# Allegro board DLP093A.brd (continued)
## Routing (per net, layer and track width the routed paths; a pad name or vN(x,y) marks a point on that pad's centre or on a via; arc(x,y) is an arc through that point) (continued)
DDBP13: length 61.9
  06_SIG2 w0.094: v1(51.81,58.2) 51.81,58.6 51.7,58.71 51.55,58.71 51.3,58.46 51.3,56.19 50.87,55.76 47.83,55.76 47.35,55.28 47.35,47.22 48.56,46.01 48.56,41.22 48.25,40.91 47.65,40.91 47.31,41.26 47.31,45.34 47.12,45.53 46.76,45.53 46.57,45.34 46.57,41.21 46.26,40.9 45.56,40.9 45.25,41.21 45.25,45.41 45.07,45.59 44.7,45.59 44.48,45.36 44.48,40.43 44.77,40.14 50.76,40.14 54.01,36.89 54.01,32.86 53.55,32.4 53.22,32.4 53.11,32.29 v1(53.11,31.89)
  BOTTOM w0.213: U500.R20 v1(53.11,31.89)
DDBP15: length 61.9
  04_SIG1 w0.094: v1(53.08,56.93) 52.79,56.93 52.67,57.05 52.67,57.33 52.82,57.48 53.58,57.48 54.21,56.84 54.21,48.95 52.57,47.31 52.57,41.91 52.35,41.69 51.88,41.69 51.65,41.92 51.65,47.52 53.43,49.3 53.43,55.82 53.11,56.14 52.49,56.14 52.17,55.83 52.17,49.8 50.4,48.03 50.4,40.4 51.37,39.43 51.37,35.05 52.35,34.07 52.35,32.85 52.15,32.65 51.95,32.65 51.84,32.76 v1(51.84,33.16)
  BOTTOM w0.213: v1(51.84,33.16) U500.T19
DMDRSTZ: length 145.6
  TOP w0.187: v1(78.25,36.45) 77.94,36.76 U1.59
  04_SIG1 w0.135: v1(35.3,62.01) 35.97,61.34 36.86,61.34 37.2,61 37.2,56.44 36.15,55.39 36.15,48.25 26.08,38.18 26.08,15.85 26.65,15.28 31.87,15.28 v1(33.05,14.11) 43.28,3.88 77.92,3.88 78.51,4.47 78.51,13.3 TP25.1 78.65,16.47 78.65,36.05 v1(78.25,36.45)
  BOTTOM w0.213: v1(33.05,14.11) U500.B9
MBRST0: length 85.1
  TOP w0.178: U1.22 v1(68.23,48.79)
  04_SIG1 w0.135: v1(68.23,48.79) 68.27,48.79 69.02,48.04 69.02,46.04 68.57,45.59 67.94,45.59 66.98,44.63 66.98,40.17 67.32,39.84 67.32,30.41 62.28,25.37 62.28,18.74 TP2.1
  06_SIG2 w0.135: v1(25.43,15.38) 26.08,14.73 26.08,13.84 26.42,13.51 38.7,13.51 40.06,12.14 47.72,12.14 48.17,11.7 58.58,11.7 59.33,12.45 63.32,12.45 TP2.1
  BOTTOM w0.178: v1(25.43,15.38) U500.C3
MBRST1: length 99.1
  TOP w0.178: U1.24 v1(68.23,47.79)
  04_SIG1 w0.135: TP3.1 61.11,13.05 61.11,25.98 64.75,29.62 64.75,37.79 64.95,37.99 64.95,41.03 64.69,41.28 64.69,44.48 65.32,45.1 65.84,45.1 68.23,47.49 v1(68.23,47.79)
  06_SIG2 w0.135: v1(24.16,16.65) 23.75,16.65 23.15,16.05 22.56,16.05 22.25,15.74 22.25,13.64 26.21,9.68 48.7,9.68 49.07,10.06 59.88,10.06 60.56,10.74 63.42,10.74 TP3.1
  BOTTOM w0.178: v1(24.16,16.65) U500.D2
MBRST2: length 91.7
  TOP w0.178: U1.27 v1(68.23,46.29)
  04_SIG1 w0.135: TP4.1 66.47,13.66 66,13.66 61.67,17.98 61.67,25.6 66.67,30.61 66.67,39.57 66.42,39.83 66.42,44.91 67.8,46.29 v1(68.23,46.29)
  06_SIG2 w0.135: v1(25.43,16.65) 25.43,16.23 24.78,15.58 24.78,12.63 26.62,10.79 48,10.79 48.37,11.17 59.02,11.17 59.74,11.9 TP4.1
  BOTTOM w0.178: v1(25.43,16.65) U500.D3
MBRST3: length 98.9
  TOP w0.178: U1.29 68.01,45.29 68.28,45.02 v1(68.28,44.99)
  04_SIG1 w0.135: TP5.1 71.03,11.92 63.04,19.91 63.04,25.31 67.84,30.1 67.84,40.19 67.61,40.42 67.61,44.18 68.18,44.75 68.18,44.88 v1(68.28,44.99)
  06_SIG2 w0.135: TP5.1 65.48,9.74 63.95,11.27 60,11.27 59.34,10.61 48.58,10.61 48.19,10.22 26.41,10.22 23.54,13.09 23.54,15.64 23.92,16.02 24.39,16.02 24.78,16.41 24.78,17.3 v1(24.16,17.92)
  BOTTOM w0.178: v1(24.16,17.92) U500.E2
MBRST4: length 107.7
  TOP w0.178: U1.32 v1(68.23,43.79)
  04_SIG1 w0.135: TP6.1 60.54,10.07 60.54,26.4 63.93,29.79 63.93,37.8 64.43,38.29 64.43,40.35 64.01,40.77 64.01,45.04 65.4,46.43 66.07,46.43 67.47,47.83 67.47,48.89 67.98,49.4 68.77,49.4 69.12,49.05 70.14,49.05 70.6,48.6 70.6,46.23 68.23,43.87 v1(68.23,43.79)
  06_SIG2 w0.135: v1(25.43,20.46) 24.76,19.79 24.76,18.95 24.35,18.54 22.63,18.54 21.1,17.01 21.1,13.25 25.74,8.61 49.38,8.61 49.73,8.96 60.35,8.96 60.63,9.23 TP6.1
  BOTTOM w0.178: v1(25.43,20.46) U500.G3
MBRST5: length 104.6
  TOP w0.178: U1.34 v1(68.23,42.79)
  04_SIG1 w0.135: v1(68.23,42.79) 69.04,41.99 69.04,39.75 68.36,39.07 68.36,29.87 63.61,25.12 63.61,20.52 73.57,10.56 73.57,7.98 TP7.1
  06_SIG2 w0.135: TP7.1 72.45,6.86 65.46,6.86 62.14,10.18 60.76,10.18 60.11,9.53 49.56,9.53 49.15,9.13 26.01,9.13 21.66,13.48 21.66,16.7 v1(22.89,17.92)
  BOTTOM w0.178: v1(22.89,17.92) U500.E1
MBRST6: length 111.7
  TOP w0.178: TP8.1 70.9,12.03 62.94,19.99 62.94,36.47 64.79,38.31 64.79,40.31 65.76,41.29 U1.37
  06_SIG2 w0.135: v1(24.16,20.46) 23.56,19.86 22.58,19.86 20.58,17.87 20.58,12.68 26.19,7.07 49.51,7.07 50.81,8.37 62,8.37 64.2,6.17 73.13,6.17 74.67,7.71 74.67,11.05 TP8.1
  BOTTOM w0.178: v1(24.16,20.46) U500.G2
MBRST7: length 113.4
  TOP w0.178: U1.39 67.87,40.29 68.15,40 68.15,38.15 63.79,33.79 63.79,20.66 69.63,14.82 TP9.1
  06_SIG2 w0.135: TP9.1 73.19,14.82 75.22,12.79 75.22,7.39 73.46,5.63 63.67,5.63 61.49,7.8 51.35,7.8 50.05,6.5 24.92,6.5 20.04,11.38 20.04,18.24 22.25,20.46 v1(22.89,20.46)
  BOTTOM w0.178: v1(22.89,20.46) U500.G1
MBRST8: length 134.4
  TOP w0.178: U1.62 v1(81.7,40.29)
  04_SIG1 w0.135: TP10.1 82.35,8.87 82.35,25.15 81.7,25.8 81.7,34.35 82.47,35.12 82.47,37.3 81.7,38.08 v1(81.7,40.29)
  06_SIG2 w0.135: TP10.1 80.93,5.96 77.32,2.35 24.27,2.35 15.84,10.78 15.84,19.52 21.63,25.32 21.63,29.98 22.19,30.53 24.57,30.53 25.43,29.67 v1(25.43,29.35)
  BOTTOM w0.178: v1(25.43,29.35) U500.N3
MBRST9: length 121.8
  TOP w0.178: v1(81.7,41.3) 81.68,41.29 U1.64
  04_SIG1 w0.135: v1(81.7,41.3) 81.04,40.65 81.04,37.88 81.92,37.01 81.92,35.32 81.04,34.45 81.04,25.41 81.66,24.79 81.66,18.22 TP11.1
  06_SIG2 w0.135: TP11.1 77.33,13.88 77.33,7.86 74,4.53 25.27,4.53 18.87,10.92 18.87,19.46 22.37,22.96 23.72,22.96 24.77,24.01 24.77,27.47 v1(24.16,28.08)
  BOTTOM w0.178: v1(24.16,28.08) U500.M2
MBRST10: length 135.7
  TOP w0.178: U1.67 81.61,42.79 81.77,42.95 v1(81.77,43.31)
  04_SIG1 w0.135: v1(81.77,43.31) 82.28,43.31 83.19,42.4 83.19,37.99 84.02,37.16 84.02,35.16 82.75,33.9 82.75,28.86 83.14,28.48 83.14,15.79 TP12.1
  06_SIG2 w0.135: TP12.1 84.24,13.62 79.44,8.83 79.44,5.22 77.13,2.91 24.5,2.91 16.42,10.99 16.42,19.31 22.06,24.95 23.14,24.95 23.5,25.31 23.5,28.35 23.84,28.69 24.44,28.69 25.05,28.08 v1(25.43,28.08)
  BOTTOM w0.178: v1(25.43,28.08) U500.M3
MBRST11: length 120.8
  TOP w0.178: U1.69 81.31,43.79 81.77,44.24 v1(82.29,44.24)
  04_SIG1 w0.135: v1(24.16,26.81) 23.57,26.22 23.57,15.03 23.91,14.69 30.76,14.69 31.12,14.32 31.12,13.87 31.53,13.46 32.03,13.46 32.4,13.09 32.4,12.52 41.59,3.33 78.58,3.33 TP13.1 85.6,10.34 85.6,36.87 84.19,38.28 84.19,42.51 82.45,44.24 v1(82.29,44.24)
  BOTTOM w0.178: v1(24.16,26.81) U500.L2
MBRST12: length 138.6
  TOP w0.178: v1(81.7,45.3) 81.68,45.29 U1.72
  04_SIG1 w0.135: TP14.1 75.23,18.38 75.23,30.09 74.39,30.93 74.39,34.59 75.49,35.69 75.49,37.19 75.7,37.4 75.7,39.74 76.52,40.56 76.52,48.32 79.26,51.06 83.03,51.06 84.31,49.77 84.31,47.02 82.6,45.3 v1(81.7,45.3)
  06_SIG2 w0.135: TP14.1 75.98,15.33 75.98,7.36 73.7,5.08 63.18,5.08 61.03,7.24 51.93,7.24 50.63,5.94 24.62,5.94 19.43,11.13 19.43,19.17 22.64,22.37 23.89,22.37 25.43,23.91 v1(25.43,24.27)
  BOTTOM w0.178: v1(25.43,24.27) U500.J3
MBRST13: length 117.9
  TOP w0.178: v1(83.02,46.74) 82.57,46.29 U1.74
  04_SIG1 w0.135: TP15.1 76.87,30.46 77.6,31.19 77.6,37.93 76.95,38.57 76.95,39.42 77.42,39.89 77.97,39.89 78.4,40.32 78.4,46.62 81.63,49.85 82.5,49.85 83.71,48.64 83.71,47.43 v1(83.02,46.74)
  06_SIG2 w0.135: v1(22.89,26.81) 22.24,27.45 22.24,29.57 22.65,29.98 24.38,29.98 24.77,29.59 24.77,29.18 25.2,28.75 25.65,28.75 26.02,28.38 26.02,15.85 27.03,14.83 48.1,14.83 48.68,14.25 48.68,12.69 49.11,12.25 58.22,12.25 59.05,13.09 62.58,13.09 65.8,16.3 71.09,16.3 74.94,20.15 TP15.1
  BOTTOM w0.178: v1(22.89,26.81) U500.L1
MBRST14: length 127.2
  TOP w0.178: v1(82.02,48.12) 81.83,48.12 81.5,47.79 U1.77
  04_SIG1 w0.135: TP16.1 80.42,23.33 80.42,46.71 81.83,48.12 v1(82.02,48.12)
  06_SIG2 w0.135: TP16.1 82.28,21.47 82.28,16.7 78.03,12.45 78.03,7.68 74.36,4 25,4 18.31,10.69 18.31,19.71 22.14,23.54 23.42,23.54 v1(24.16,24.27)
  BOTTOM w0.178: v1(24.16,24.27) U500.J2
MBRST15: length 129.2
  TOP w0.178: U1.79 81.57,48.79 v1(81.91,49.13)
  04_SIG1 w0.135: TP17.1 79.78,13.81 79.78,47 v1(81.91,49.13)
  06_SIG2 w0.135: v1(22.89,24.27) 22.11,24.27 16.95,19.11 16.95,11.26 24.79,3.43 74.75,3.43 78.71,7.39 78.71,10.19 TP17.1
  BOTTOM w0.178: v1(22.89,24.27) U500.J1
MODE_A: length 5.4
  TOP w0.187: v1(26.7,12.84) 26.45,12.59 R2.1 R1.2
  BOTTOM w0.213: v1(26.7,12.84) U500.A4
Net_122:
  vias: v1(42.92,60.74)
Net_123:
  vias: v1(42.92,62.01)
Net_124:
  vias: v1(44.19,62.01)
Net_125:
  vias: v1(44.19,63.28)
Net_126:
  vias: v1(45.46,60.74)
Net_127:
  vias: v1(45.46,62.01)
Net_128:
  vias: v1(48,60.74)
Net_129:
  vias: v1(48,62.01)
Net_130:
  vias: v1(49.27,62.01)
Net_131:
  vias: v1(49.27,63.28)
Net_132:
  vias: v1(50.54,60.74)
Net_133:
  vias: v1(50.54,62.01)
Net_134:
  vias: v1(51.81,62.01)
Net_135:
  vias: v1(51.81,63.28)
Net_136:
  vias: v1(23.87,62.01)
Net_137:
  vias: v1(23.87,63.28)
Net_138:
  vias: v1(25.14,60.74)
Net_139:
  vias: v1(25.14,62.01)
Net_140:
  vias: v1(26.41,62.01)
Net_141:
  vias: v1(26.41,63.28)
Net_142:
  vias: v1(27.68,60.74)
Net_143:
  vias: v1(27.68,62.01)
Net_144:
  vias: v1(30.22,60.74)
Net_145:
  vias: v1(30.22,62.01)
Net_146:
  vias: v1(31.49,62.01)
Net_147:
  vias: v1(31.49,63.28)
Net_148:
  vias: v1(32.76,60.74)
Net_149:
  vias: v1(32.76,62.01)
Net_150:
  vias: v1(34.03,62.01)
Net_151:
  vias: v1(34.03,63.28)
Net_152:
  vias: v1(35.3,56.93)
Net_153:
  vias: v1(36.57,59.47)
Net_154:
  vias: v1(36.57,62.01)
Net_155:
  vias: v1(41.65,62.01)
Net_156:
  vias: v1(41.65,63.28)
SCP_DAD_CSZ: length 167.8
  TOP w0.187: U1.58 77.44,38.98 v1(77.58,39.12)
  06_SIG2 w0.135: v1(77.58,39.12) 77.58,38.04 84.61,31.01 TP21.1 85.13,25.21 85.13,12.87 81.98,9.72 81.98,6.16 77.61,1.79 24.06,1.79 15.3,10.55 15.3,19.77 19.92,24.39 19.92,38.48 34.62,53.19 34.62,57.14 35.08,57.59 35.96,57.59 v1(36.57,58.2)
SCPCLK: length 152.6
  TOP w0.187: v1(76.33,39.12) 76.44,39 U1.56
  04_SIG1 w0.135: v1(34.03,59.47) 33.46,58.9 33.46,51.59 20.64,38.76 20.64,14.97 24.67,10.94 29.88,10.94 v1(31.78,12.84)
  BOTTOM w0.213: U500.A8 v1(31.78,12.84) 32.56,12.06 65.14,12.06 TP18.1 71.29,7.7 75.22,11.63 75.22,14.6 79.25,18.63 79.25,26.23 85.41,32.38 85.41,36.98 83.95,38.44 77,38.44 v1(76.33,39.12)
SCPDI: length 155.9
  TOP w0.187: R4.1 v1(85.98,37.55) ; v1(27.29,11.6) 28.66,10.23 R3.1
  BOTTOM w0.213: v1(85.98,37.55) 86.2,37.34 86.2,29.7 82.89,26.4 82.89,7.53 78.69,3.32 63.25,3.32 57.13,9.44 29.44,9.44 v1(27.29,11.6) 25.48,11.6 21.85,15.23 21.85,33.36 33.36,44.88 33.36,61.1 33.6,61.33 34.71,61.33 v1(35.3,60.74)
SCPDI_DAD: length 21.3
  TOP w0.187: v1(83.37,36.47) 83.38,36.49 R4.2 ; U1.42 v1(69.44,39.08)
  BOTTOM w0.213: TP20.1 83.94,33.78 83.94,36.24 83.7,36.47 v1(83.37,36.47) 82.09,37.76 70.76,37.76 v1(69.44,39.08)
SCPDI_RS: length 4.8
  TOP w0.187: R3.2 31.84,10.23 33.05,11.43 v1(33.05,12.84)
  BOTTOM w0.213: U500.A9 v1(33.05,12.84)
SCPDO: length 144.9
  TOP w0.187: v1(76.79,36.21) 76.95,36.36 U1.57
  04_SIG1 w0.135: v1(76.79,36.21) 76.79,31.57 75.95,30.73 75.95,6.47 TP19.1 ; v1(34.03,58.2) 34.64,57.59 34.64,50.71 21.35,37.42 21.35,15.24 24.36,12.23 27.35,12.23 v1(27.97,12.84)
  BOTTOM w0.213: U500.A5 v1(27.97,12.84) 30.4,10.4 58.06,10.4 63.68,4.79 TP19.1
SCPENZ: length 59.3
  04_SIG1 w0.135: v1(35.3,58.2) 35.92,57.58 35.92,56.66 35.47,56.21 35.47,49.59 21.9,36.02 21.9,15.54 23.96,13.48 29.88,13.48 v1(30.51,14.11)
  BOTTOM w0.213: U500.B7 v1(30.51,14.11)
SCTRLAN: length 111.8
  06_SIG2 w0.094: v1(28.95,63.28) 28.95,62.88 29.06,62.77 29.21,62.77 29.45,63.02 29.45,63.8 29.75,64.09 42.12,64.09 42.31,64.28 42.31,64.62 42.05,64.88 30.42,64.88 29.94,65.36 29.94,66.14 30.4,66.6 55.48,66.6 60.57,61.5 60.57,58.48 56.62,54.53 56.62,41.57 58.72,39.48 58.72,24.55 53.85,19.68 52.93,19.68 52.63,19.39 52.63,18.82 52.83,18.63 52.96,18.63 53.11,18.78 v1(53.11,19.19)
  BOTTOM w0.213: U500.F20 v1(53.11,19.19)
SCTRLAP: length 111.8
  06_SIG2 w0.094: v1(53.11,17.92) 53.14,17.95 53.14,18.27 53.03,18.38 52.72,18.38 52.38,18.72 52.38,19.49 52.82,19.93 53.74,19.93 58.46,24.65 58.46,39.37 56.37,41.47 56.37,54.63 60.32,58.58 60.32,61.4 55.37,66.35 30.5,66.35 30.19,66.04 30.19,65.46 30.53,65.13 42.16,65.13 42.56,64.73 42.56,64.18 42.22,63.84 29.85,63.84 29.71,63.69 29.71,62.91 29.32,62.52 29.06,62.52 28.91,62.37 28.91,62.05 v1(28.95,62.01)
  BOTTOM w0.213: v1(53.11,17.92) U500.E20
SCTRLBN: length 62
  06_SIG2 w0.094: v1(53.11,26.81) 53.54,27.23 53.77,27.23 54.23,27.69 54.23,31.66 55.14,32.57 55.14,37.5 49.85,42.79 49.85,46.52 48.48,47.9 48.48,54.56 48.77,54.86 49.33,54.86 49.59,54.59 49.59,48.86 50.06,48.38 50.74,48.38 51.2,48.84 51.2,54.58 52.57,55.95 52.57,62.33 52.13,62.77 46.88,62.77 46.73,62.92 v1(46.73,63.28)
  BOTTOM w0.213: U500.L20 v1(53.11,26.81)
SCTRLBP: length 61.9
  06_SIG2 w0.094: v1(53.11,28.08) 52.95,28.08 52.85,27.99 52.85,27.63 53,27.49 53.67,27.49 53.97,27.79 53.97,31.76 54.88,32.67 54.88,37.39 49.59,42.68 49.59,46.42 48.22,47.79 48.22,54.67 48.67,55.11 49.44,55.11 49.85,54.7 49.85,48.96 50.17,48.64 50.63,48.64 50.95,48.95 50.95,54.68 52.32,56.06 52.32,62.22 52.02,62.52 46.83,62.52 46.73,62.42 v1(46.73,62.01)
  BOTTOM w0.213: v1(53.11,28.08) U500.M20
VBIAS: length 47.3
  TOP w0.305: v1(82.48,39.77) 82.36,39.64 81.25,39.64 81.1,39.79 U1.61 ; 79.11,44.53 79.36,44.29 U1.70 ; 79.11,44.53 v1(79.18,44.53) ; 79.11,44.53 79.37,44.79 U1.71 ; U1.31 65.88,44.29 v1(65.69,44.47) 66.01,44.79 U1.30 ; U1.9 v1(74.44,50) ; 84.89,55.41 C19.2 ; C19.2 86.11,51.45 ; C19.2 84.89,51.45 ; C19.2 86.11,55.41 ; D2.1 85.88,55.66 ; D2.1 85.88,57.54 ; D2.1 84.47,57.54 ; D2.1 84.47,55.66 ; v1(65.63,49.3) 65.64,49.29 U1.21 ; v1(65.69,39.78) 66.98,39.78 U1.40 ; U1.80 v1(79.16,49.29)
  TOP w0.508: v1(65.69,44.47) 63.98,44.47 C27.2 ; v1(65.69,39.78) TP26.1 ; C18.2 85.31,59.59 85.78,60.05 v1(85.78,60.35) ; v1(84.87,42.19) C30.2 83.63,42.19 82.6,41.15 82.6,39.89 v1(82.48,39.77)
  TOP w1.016: C18.2 85.31,56.74 D2.1 85.26,56.52 85.26,53.67 C19.2 85.5,51.6 v1(85.63,51.47)
  06_SIG2 w0.305: 65.02,36.88 TP26.1 ; TP26.1 65.02,38.22 ; TP26.1 66.36,38.22 ; TP26.1 66.36,36.88
  vias: v1(84.86,60.33)
VBIAS_LHI: length 17.8
  TOP w0.305: 75.16,54.67 73.94,53.46 U1.10
  TOP w0.762: C17.2 77.95,56.01 76.79,54.85 75.33,54.85 75.16,54.67
  TOP w1.016: C10.1 77.89,66.19 77.89,62.32 L4.1 C17.2
VRST: length 76.5
  TOP w0.305: C20.2 84.76,49.25 ; C20.2 TP27.1 ; C20.2 82.94,49.25 ; C20.2 84.76,47.06 ; TP27.1 84.86,47.49 ; TP27.1 84.86,48.83 ; v1(79.16,42.06) 79.43,41.79 U1.65 ; v1(79.16,42.06) 78.39,42.06 78.38,42.04 ; v1(79.16,42.06) 79.38,42.29 U1.66 ; 68.07,42.07 67.86,42.29 U1.35 65.54,42.29 v1(65.31,42.06) 65.59,41.79 U1.36 67.78,41.79 68.07,42.07 ; 68.07,42.07 69.14,42.07 69.15,42.08 ; U1.13 72.44,52.24 71.82,52.87 71.82,54.1 ; v1(81.9,47.04) 81.9,47.02 81.67,46.79 U1.75 78.42,46.79 78.41,46.8 ; v1(81.9,47.04) 83,48.14 v1(83,48.16) ; v1(81.9,47.04) 81.9,47.06 81.67,47.29 U1.76 78.41,47.29 78.41,47.28 ; 68.02,47.07 67.8,47.29 U1.25 65.9,47.29 v1(65.67,47.05) 65.93,46.79 U1.26 67.73,46.79 68.02,47.07 ; 68.02,47.07 69.05,47.07 69.06,47.07
  TOP w0.508: C28.2 64.04,42.06 v1(65.31,42.06) ; v1(83,48.16) C20.2
  TOP w0.762: C16.2 v1(70.71,55.21) 71.82,54.1
  TOP w1.016: C15.2 69.57,58.15 70.71,57.01 C16.2 D1.2
  02_PWR w0.305: 84.86,47.49 TP27.1 84.86,48.83
  04_SIG1 w0.508: v1(70.71,55.21) 70.07,55.21 66.46,51.59 66.46,47.84 v1(65.67,47.05)
  BOTTOM w0.305: 84.86,48.83 TP27.1 84.86,47.49
  BOTTOM w0.762: v1(65.67,47.05) 63.92,45.31 63.92,43.45 v1(65.31,42.06) ; v1(81.9,47.04) 80.54,45.68 80.54,42.82 79.78,42.06 v1(79.16,42.06) ; v1(83,48.16) TP27.1
  vias: v2(69.88,48.35) v2(69.88,46.44) v2(69.88,44.54) v2(69.88,42.63) v2(69.88,40.73) v2(71.79,48.35) v2(71.79,46.44) v2(71.79,44.54) v2(71.79,42.63) v2(71.79,40.73) v2(73.69,48.35) v2(73.69,46.44) v2(73.69,44.54) v2(73.69,42.63) v2(73.69,40.73) v2(75.6,48.35) v2(75.6,46.44) v2(75.6,44.54) v2(75.6,42.63) v2(75.6,40.73) v2(77.5,48.35) v2(77.5,46.44) v2(77.5,44.54) v2(77.5,42.63) v2(77.5,40.73)
VRST_SWL: length 11.6
  TOP w0.305: U1.12 72.94,54.13 73.65,54.84
  TOP w0.508: D1.1 75.42,56.6 73.65,54.84
  TOP w1.016: L3.2 75.15,59.33 76.28,58.2 D1.1
N28103: length 12.9
  TOP w0.305: C1.1 21.22,47.97 ; C1.1 20.38,47.76 20.29,47.67 ; C1.1 20.38,49.53 20.31,49.6 ; C1.1 21.22,49.23 ; 23.84,49.59 23.89,49.55 L1.1 ; L1.1 23.05,47.97 ; L1.1 23.89,47.7 23.9,47.69 ; L1.1 23.05,49.23
  TOP w0.508: L1.1 v1(22.59,48.6) v1(21.36,48.6) C1.1 ; v1(22.6,58.2) v1(22.6,56.93)

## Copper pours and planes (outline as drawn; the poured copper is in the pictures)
GND on TOP (solid shape): 87.23,72.7 0.76,72.7 0.76,73.24 87.23,73.24
GND on TOP (solid shape): 87.23,0.77 0.76,0.77 0.76,1.3 87.23,1.3
GND on TOP (solid shape): 87.23,0.76 86.7,0.76 86.7,73.24 87.23,73.24
GND on BOTTOM (solid shape): 87.23,72.7 0.76,72.7 0.76,73.24 87.23,73.24
GND on BOTTOM (solid shape): 87.23,0.77 0.76,0.77 0.76,1.3 87.23,1.3
GND on BOTTOM (solid shape): 87.23,0.76 86.7,0.76 86.7,73.24 87.23,73.24
GND on 02_PWR (solid shape): 87.23,72.7 0.76,72.7 0.76,73.24 87.23,73.24
GND on 02_PWR (solid shape): 87.23,0.77 0.76,0.77 0.76,1.3 87.23,1.3
GND on 02_PWR (solid shape): 87.23,0.76 86.7,0.76 86.7,73.24 87.23,73.24
GND on 03_GND1 (solid shape): 87.23,72.7 0.76,72.7 0.76,73.24 87.23,73.24
GND on 03_GND1 (solid shape): 87.23,0.77 0.76,0.77 0.76,1.3 87.23,1.3
GND on 03_GND1 (solid shape): 87.23,0.76 86.7,0.76 86.7,73.24 87.23,73.24
GND on 04_SIG1 (solid shape): 87.23,72.7 0.76,72.7 0.76,73.24 87.23,73.24
GND on 04_SIG1 (solid shape): 87.23,0.77 0.76,0.77 0.76,1.3 87.23,1.3
GND on 04_SIG1 (solid shape): 87.23,0.76 86.7,0.76 86.7,73.24 87.23,73.24
GND on 05_GND2 (solid shape): 87.23,72.7 0.76,72.7 0.76,73.24 87.23,73.24
GND on 05_GND2 (solid shape): 87.23,0.77 0.76,0.77 0.76,1.3 87.23,1.3
GND on 05_GND2 (solid shape): 87.23,0.76 86.7,0.76 86.7,73.24 87.23,73.24
GND on 06_SIG2 (solid shape): 87.23,72.7 0.76,72.7 0.76,73.24 87.23,73.24
GND on 06_SIG2 (solid shape): 87.23,0.77 0.76,0.77 0.76,1.3 87.23,1.3
GND on 06_SIG2 (solid shape): 87.23,0.76 86.7,0.76 86.7,73.24 87.23,73.24
GND on 07_GND3 (solid shape): 87.23,72.7 0.76,72.7 0.76,73.24 87.23,73.24
GND on 07_GND3 (solid shape): 87.23,0.77 0.76,0.77 0.76,1.3 87.23,1.3
GND on 07_GND3 (solid shape): 87.23,0.76 86.7,0.76 86.7,73.24 87.23,73.24
GND on TOP: 81.21,35.84 84.82,35.84 85.31,35.35 85.31,28.49 84.58,27.76 81.27,27.76 80.99,28.05 80.99,35.62
GND on TOP: 67.04,28.99 75.07,28.99 75.33,29.24 75.33,32.01 74.97,32.37 71.82,32.37 71.43,32.76 67.04,32.76 66.78,32.5 66.78,29.24
GND on TOP: 37.49,36.39 49.08,36.39 49.33,36.64 49.33,38.72 49.14,38.91 37.52,38.91 37.22,38.61 37.22,36.66
GND on TOP: 67.5,62.21 70.27,62.21 71.61,60.87 76.44,60.87 76.82,61.25 76.82,66.23 76.17,66.88 67.94,66.88 67.24,66.18 67.24,62.47
GND on TOP: 40.83,7.37 48.26,7.37 48.55,7.66 48.55,9.1 48.17,9.48 40.89,9.48 40.53,9.12 40.53,7.68
GND on TOP: 79.83,64.39 82.24,64.39 82.5,64.64 82.5,68.34 82.24,68.59 79.83,68.59 79.58,68.34 79.58,64.64
GND on TOP: 9.08,71.03 21.31,71.03 22.11,70.24 22.11,68.55 22.07,68.55 21.65,68.13 12.58,68.13 11.98,67.53 11.98,53.24 13.1,52.11 16.36,52.11 19.32,49.16 19.32,47.23 22.8,43.75 33.48,43.75 34.07,43.16 34.07,31.94 33.51,31.37 28.76,31.37 27,33.13 20.23,33.13 20.23,33.11 19.17,32.05 19.17,14.89 15.5,11.22 15.5,5.13 15.03,4.66 8.79,4.66 6.49,6.96 6.49,11.89 4.12,14.26 4.12,16.61 4.8,17.29 9.75,17.29 12.47,20.01 12.47,27.76 10.81,29.43 3.9,29.43 2.92,30.41 2.92,62.1 7.34,66.53 7.34,69.3
GND on BOTTOM: 69.11,32.6 76.06,32.6 76.36,32.3 76.36,29.97 76,29.62 69.18,29.62 68.8,30 68.8,32.3
GND on BOTTOM: 19.02,64.49 15.7,61.17 15.7,52.77 18.17,50.3 18.17,43.47 20.51,41.12 20.51,13.03 25.05,8.5 48.45,8.5 48.8,8.14 48.8,3.17 47.65,2.02 11.27,2.02 2.86,10.42 2.86,15.68 4.01,16.83 12.06,16.83 13.38,18.14 13.38,28.24 11.62,30 2.96,30 2.25,30.7 2.25,63.24 11.13,72.12 75.4,72.12 75.76,71.77 75.76,70.15 75.24,69.63 42.16,69.63 37.02,64.49
GND on 03_GND1, 07_GND3: 0.76,0.76 0.76,20.21 1.33,20.21 1.33,27.3 0.76,27.3 0.76,73.24 87.24,73.24 87.24,0.76
GND on 04_SIG1: 64.29,71.78 78.64,71.78 82.56,67.86 82.56,56.22 81.81,55.47 77.6,55.47 76.62,56.45 76.62,67.13 76.06,67.7 74.79,67.7 74.32,67.23 74.32,54.08 71.6,51.36 68.94,51.36 68.54,51.76 68.54,52.56 70.95,54.97 70.95,56.66 67.98,59.63 67.98,66.11 63.94,70.15 63.94,71.43
GND on 04_SIG1: 9.42,71.66 22.31,71.66 23.04,70.93 23.04,56.79 24.09,55.74 29.4,55.74 30.97,54.17 30.97,51 19.4,39.43 19.4,13.61 23.2,9.8 33.3,9.8 34.33,8.77 34.33,3.09 33.53,2.29 10.2,2.29 3.25,9.24 3.25,15.81 4.14,16.7 10.01,16.7 12.69,19.38 12.69,27.78 11.09,29.38 4.09,29.38 3.01,30.46 3.01,65.25
GND on 05_GND2: 0.76,0.76 0.76,20.2 1.34,20.2 1.34,27.23 0.76,27.23 0.76,73.24 87.24,73.24 87.24,0.76
GND on 06_SIG2: 63.72,71.61 79.07,71.61 82.62,68.06 82.62,63.25 81.94,62.57 69.96,62.57 63.02,69.52 63.02,70.9
GND on 06_SIG2: 78.4,34.8 78.4,29.08 77.56,28.24 65.87,28.24 65.16,28.94 65.16,32.2 68.59,35.63 77.57,35.63
GND on 06_SIG2: 9.27,71.25 21.92,71.25 22.95,70.22 22.95,68.55 16.05,61.65 16.05,57.69 18.78,54.96 29.72,54.96 30.98,53.69 30.98,51.13 18.89,39.04 18.89,24.3 14.84,20.26 14.84,4.44 14.42,4.02 8.08,4.02 2.36,9.75 2.36,16.09 3.44,17.17 8.55,17.17 11.98,20.6 11.98,28.11 10.2,29.89 3.53,29.89 2.5,30.92 2.5,64.48
P12V on TOP: 72.32,36.21 74.04,36.21 74.42,35.84 74.42,32.85 74.26,32.7 72.03,32.7 71.84,32.88 71.84,35.73
P12V on BOTTOM: 71.52,32.83 76.29,32.83 76.55,33.1 76.55,36.21 76.23,36.53 67.5,36.53 67.02,36.05 58.45,36.05 47.04,47.45 38.89,47.45 38.03,46.59 38.03,42.98 38.74,42.27 46.22,42.27 56.69,31.8 67.54,31.8 69.42,33.67 70.68,33.67
P12V on 04_SIG1: 42.09,62.92 42.56,62.45 42.56,58.54 41.41,57.39 41.41,55.63 40.21,54.42 40.21,44.09 39.61,43.49 37.57,43.49 37.24,43.82 37.24,54.96 38.22,55.94 38.22,62.57 38.57,62.92
P12V on 04_SIG1: 73.52,50.72 75.17,50.72 75.22,50.67 75.22,39.1 73.93,37.81 73.93,34.97 73.71,34.75 70.48,34.75 70.17,35.07 70.17,44.6 71.09,45.52 71.09,49.02 71.63,49.56 72.37,49.56
V12_SWL-NC on 06_SIG2: 72.45,39.7 75.71,39.7 75.92,39.49 75.92,36.16 75.68,35.91 72.19,35.91 71.99,36.11 71.99,39.24
VCC on TOP: 37.66,36.26 37.25,35.85 37.25,31.74 37.74,31.24 49.82,31.24 50.33,31.76 50.33,35.86 49.94,36.26
VCC on TOP: 54.85,48.76 54.85,41.6 55.09,41.35 58.76,41.35 58.93,41.53 58.93,43.74 58.15,44.53 58.15,46.19 57.06,46.19 56.8,46.44 56.8,48.81 56.42,49.19 55.28,49.19
VCC on TOP: 25.14,47.34 27.67,47.34 27.91,47.58 27.91,49.73 27.71,49.93 25.19,49.93 24.83,49.56 24.83,47.66
VCC on TOP: 40.95,9.6 48.82,9.6 49.16,9.94 49.16,14.26 48.68,14.74 41.02,14.74 40.48,14.2 40.48,10.07
VCC on 02_PWR: 1.05,0.85 1.05,72.99 87.16,72.99 87.16,64.04 66.54,64.04 62.63,60.12 62.63,57.51 62.4,57.28 62.4,36.52 58.33,32.44 58.33,8.19 57.71,7.58 53.1,7.58 52.54,7.01 52.54,0.85
VCC2 on TOP: 74.96,35.48 74.96,33.98 75.12,33.82 76.53,33.82 76.66,33.7 76.66,32.22 75.95,31.52 75.95,27.36 76.93,26.39 78.83,26.39 79.36,26.91 79.36,35.21 78.77,35.8 75.29,35.8
VCC2 on TOP: 18.3,1.96 16.7,3.56 16.7,11.78 19.56,14.64 19.56,31.6 19.9,31.94 25.72,31.94 26.07,31.59 26.07,13.99 23.28,11.19 23.28,7.9 24.04,7.14 57.95,7.14 58.29,6.8 58.29,2.2 58.04,1.96
VCC2 on 02_PWR: 53.06,0.85 53.06,6.53 53.72,7.2 58.19,7.2 58.71,7.72 58.71,32.28 62.71,36.28 62.71,47.99 63.45,48.73 66.23,48.73 67.09,47.87 67.09,42.64 69.65,40.08 78.14,40.08 78.67,40.6 78.67,48.3 78.98,48.61 80.52,48.61 80.76,48.37 80.76,44.62 81.44,43.95 83.44,43.95 84.48,45 87.16,45 87.16,21.19 86.9,20.93 86.9,0.85
3P3V on TOP: 58.55,44.6 60.7,44.6 60.86,44.77 60.86,48.85 61.25,49.24 64.42,49.24 66.35,51.17 66.35,61.2 66.12,61.43 63.89,61.43 63.65,61.19 63.65,52.73 63.27,52.35 58.9,52.35 58.45,51.9 58.45,44.7
3P3V on BOTTOM: 51.47,65.24 65.19,65.24 66.2,64.22 66.2,56.98 65.44,56.22 51.34,56.22 50.83,56.73 50.83,64.6
VBIAS on TOP: 84.25,51.73 85.15,50.83 86.19,50.83 86.66,51.29 86.66,60.63 86.47,60.82 84.45,60.82 84.08,60.45 84.08,57.84 84.25,57.66
VBIAS on 06_SIG2: 81.21,38.23 85.49,38.23 86.04,38.78 86.04,61.31 85.51,61.85 67.8,61.85 66.56,60.6 66.56,53.2 64.1,50.74 64.1,37.34 65,36.44 67.77,36.44 71.54,40.21 79.23,40.21
VRST on TOP (solid shape): 78.7,39.53 68.69,39.53 68.69,49.54 78.7,49.54
VRST on BOTTOM (solid shape): 78.7,39.53 68.69,39.53 68.69,49.54 78.7,49.54
VRST on TOP: 82.56,49.33 85.77,49.33 86.29,48.82 86.29,46.92 86.11,46.74 83.65,46.74 83.3,47.09 82.5,47.09 82.11,47.48 82.11,48.89
VRST on BOTTOM: 63.93,49.58 85.59,49.58 86.08,49.09 86.08,40.21 85.33,39.46 63.94,39.46 63.17,40.24 63.17,48.82
VRST on 02_PWR: 87.2,63.76 66.97,63.76 63.03,59.83 63.03,56.86 62.75,56.58 62.75,49.38 63.14,48.99 66.66,48.99 67.36,48.28 67.36,42.8 69.9,40.27 77.74,40.27 78.31,40.84 78.31,48.39 79.2,49.28 80.38,49.28 81.17,48.49 81.17,44.76 81.47,44.45 83.4,44.45 84.24,45.29 87.2,45.29
N28103 on TOP: 20.19,49.91 24.05,49.91 24.43,49.53 24.43,47.5 24.16,47.23 20.09,47.23 19.83,47.5 19.83,49.55
N28103 on BOTTOM: 20.09,58.92 24.41,58.92 24.76,58.56 24.76,48.28 23.77,47.29 19.66,47.29 19.1,47.86 19.1,57.93

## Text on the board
BOTTOM: 08_BOTTOM
Ref Des/Assembly Bottom: ASSEMBLY | 2
Board Geometry/Soldermask Bottom: MASK_BOTTOM
Ref Des/Silkscreen Bottom: SILK_BOTTOM | DLPLCR55EVM_DLP093_REV1
TOP: 01_TOP
Ref Des/Assembly Top: ASSEMBLY | 1 | 2
Board Geometry/Soldermask Top: MASK_TOP
Ref Des/Silkscreen Top: 305-PD-23-0226 | MAR-2023 | GND | DAD_IRQZ | MBRST4 | MBRST0 | MBRST1 | MBRST2 | VBIAS | SCPCLK | MBRST7 | DAD_STRB | MBRST5 | MBRST3 | MBRST6 | DMDRSTZ | SCPDO | MBRST12 | SCP_DAD_CSZ | MBRST8 | MBRST13 | VCC2 | MBRST15 | MBRST14 | MBRST10 | MBRST9 | MBRST11 | SCPDI_DAD | DAD_OEZ | VRST | SILK_TOP
02_PWR: 02_PWR
03_GND1: 03_GND1
04_SIG1: 04_SIG1
05_GND2: 05_GND2
06_SIG2: 06_SIG2
07_GND3: 07_GND3
DIMENSION: CUTOUT | PASTE_TOP | IMPEDANCE CONTROL +/- 10% | 50ohm SINGLE ENDED | 7.37 MIL | 8.37 MIL | 5.3 MIL | 100ohm DIFFERENTIAL | 3.71/6.29  MIL | -------
PLACE_BOUND_TOP: PASTE_BOTTOM
User.10: 15. TEARDROPS SHOULD NOT BE ADDED ON ANY AREA WITHOUT PRIOR APPROVAL FROM PACTRON | 16. SEE DETAIL A FOR IMPEDANCE REQUIREMENTS AND COPPER WEIGHTS | 11. MAXIMUM RATED VOLTAGE BETWEEN CONDUCTORS SHALL | BE 65 VOLTS PEAK. | 12. NO BREAKOUT ALLOWED ON PLATED THROUGH HOLES. | 13. ALL HOLES IN DRILL CHART ARE FINISHED HOLE SIZES (FHS) | 14. NO VENDOR LOGO, ART WORKS SHOULD NOT BE CHANGED WITHOUT PRIOR APPROVAL FROM PACTRON | 10. DEBURR ALL SHARP EDGES | 11. CLIP SILKSCREEN ON NO MASK AREA | 4. UL RECOGNIZED COMPONENT (ZPMV2) - FLAMMABILITY | RATING: 94V-O DIRECT SUPPORT RATING PER UL796: YES | ("DELTA" MARKING OPTIONAL) TEMPERATURE RATING: 105 | DEGREES C MINIMUM. | 5. ELECTRICAL TEST MARKINGS SHOULD BE LEGIBLE, PERMANENT | AND LOCATED ON THE SECONDARY SIDE OF THE BOARD AND | WITHSTAND WAVE SOLDER.  LOCATION SHOULD NOT BE UNDER | COMPONENTS.  UL LOGO AND 94V-O FLAMMABILITY RATING | SHOUD BE ETCHED ON THE SECONDARY SIDE OF THE BOARD. | 6. IONIC CONTAMINATION LEVEL 10 uG/IN SQ MAXIMUM. | 7. VERIFICATION OF GOLD AND NICKEL PLATING THICKNESS | REQUIRED FOR EACH FABRICATION LOT. | 2. PLATE INDICATED AREA (BOTH SIDES) WITH | ELECTROLYTIC PLATING 100-200 MICRO-INCHES OF NICKEL UNDER | 35-50 MICRO-INCHES OF GOLD. | 3. BOARD MATERIAL -REFER STACKUP | EXCEED IPC-4101B. COLOR: NATURAL. | WORKMANSHIP SHALL CONFORM TO | 6. NEED TO CUT THE BOARD AS PER MARKED DIMENSION | 7. MARKED REGION VIAS NEED TO BE SOLDERMASK PLUGGING ON BOTTOM SIDE | 8. MARKED REGION VIAS NEED TO BE NON CONDUCTIVE VIA FILLING WITH PLATED OVER | 4. APPLY LPI SILKSCREEN OR EQUIVALENT PER THE ARTWORK. | COLOR: WHITE. | 9. REMOVE UNUSED PADS IN ALL INNER LAYERS | MICRO-INCHES OF NICKEL UNDER 5-15 MICRO-INCHES OF GOLD. | BOARD MATERIAL SHALL MEET OR | FLAT AND SMOOTHE ON TOP SIDE | 2 | 8 | SEE NOTE- 6 | FAB | 7 | 4X PLACES | DETAIL-A
User.11: DLPLCR55EVM_DLP093 | 305-PD-23-0226 | 1 | MAR 2023 | PACTRON
User.16: SEE DETAIL A
User.30: FIGURE | SIZE | 10.0 | 10.01 | 12.01 | 24.02 | 134.65 | 182.01 | 66.93 | 216.54 | DRILL CHART: TOP to BOTTOM | ALL UNITS ARE IN MILS | TOLERANCE | +3.0/-3.0 | +2.0/-0.0 | +2.0/-2.0 | PLATED | NON-PLATED | QTY | 448 | 150 | 25 | 28 | 4 | 2 | 3
User.33: STACKUP: 8 LAYERS | TOTAL THICKNESS: 63 mils +/-10% | DIELECTRIC (4.24 mils) | DIELECTRIC (7.09 mils) | DIELECTRIC (6.42 mils) | DIELECTRIC (4.65 mils) | TOP (0.5 oz + PLATING) | 02_PWR (2 oz) | 03_GND1  (2 oz) | 04_SIG1 (1 oz) | 05_GND2  (2 oz) | 06_SIG2 (1 oz) | 07_GND3 (2 oz) | BOTTOM (0.5 oz + PLATING) | IT-180A
